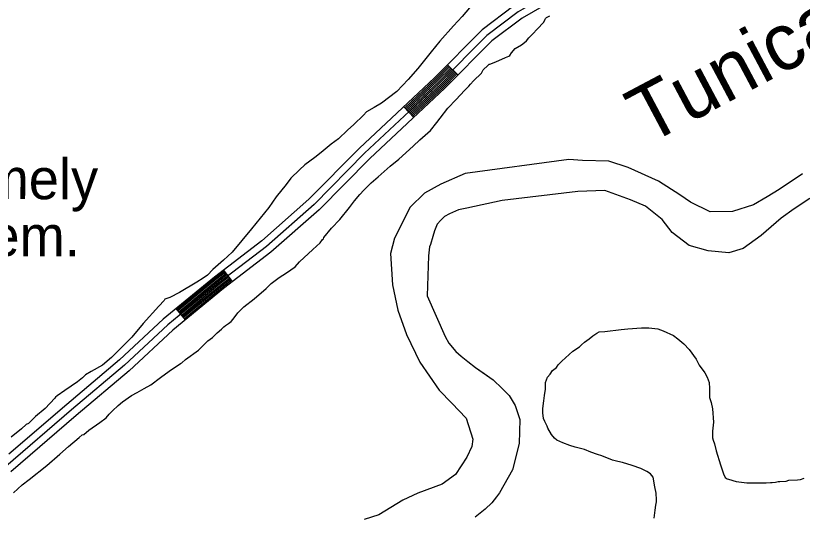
# Model space of a CAD drawing. Extents: x 3192986 to 3230865, y 867483 to 892886.
# Drawn here: x 3213297 to 3214907, y 882747 to 883775 of the extents above; entities that cross this region are included whole.
import ezdxf

# ---------------------------------------------------------------- set-up
doc = ezdxf.new("R2010")
doc.units = 0
for name, color, linetype in [('V-RIVR-IDEN', 7, 'Continuous'), ('V-ROAD-CNTR', 7, 'Continuous'), ('V-SITE-OTLN-IDEN', 7, 'Continuous'), ('V-SITE-VEGE', 7, 'Continuous'), ('V-TOPO-SHOR', 7, 'Continuous')]:
    doc.layers.add(name, color=color, linetype=linetype)

msp = doc.modelspace()

# ---------------------------------------------------------------- linework, layer by layer
at = {"layer": 'V-ROAD-CNTR'}
for p, q in [((3214202.3, 883653.8), (3214181, 883674.9)), ((3214111.7, 883566.9), (3214091.2, 883588.8)), ((3213740.6, 883230.5), (3213722.4, 883254.3)), ((3213644.1, 883151.9), (3213625, 883175.1))]:
    msp.add_line(p, q, dxfattribs=at)
for points in [[(3214950.3, 884340.7), (3214884, 884293.4), (3214837.6, 884267.8), (3214768.4, 884239.4), (3214700.1, 884199.6), (3214637.4, 884164.4), (3214595.7, 884124.3), (3214555.7, 884067.5), (3214532, 884005.1), (3214517.8, 883962.4), (3214490.3, 883932.5), (3214450.2, 883888.4), (3214388.7, 883837.2), (3214317, 883795.5), (3214251.6, 883746.2), (3214154.3, 883648), (3214000.7, 883504), (3213897.2, 883399.3), (3213800.4, 883313.9), (3213703.5, 883239.8), (3213598.5, 883153.2), (3213509.2, 883070.4), (3213401.1, 882978.8), (3213282.5, 882876.9)], [(3214959.1, 884328.6), (3214892, 884280.7), (3214844.1, 884254.2), (3214775.1, 884225.9), (3214707.6, 884186.6), (3214646.4, 884152.2), (3214607.1, 884114.4), (3214569, 884060.4), (3214546.2, 884000), (3214531, 883954.6), (3214501.3, 883922.3), (3214460.6, 883877.6), (3214397.3, 883824.8), (3214325.4, 883783), (3214261.5, 883734.9), (3214164.8, 883637.2), (3214011.1, 883493.3), (3213907.5, 883388.4), (3213809.9, 883302.3), (3213712.8, 883228), (3213608.4, 883141.9), (3213519.1, 883059.2), (3213410.8, 882967.4), (3213276.1, 882851.6)], [(3214968, 884316.5), (3214900, 884267.9), (3214850.6, 884240.7), (3214781.7, 884212.4), (3214715, 884173.6), (3214655.4, 884140.1), (3214618.5, 884104.6), (3214582.4, 884053.3), (3214560.3, 883995), (3214544.2, 883946.8), (3214512.4, 883912.2), (3214471, 883866.7), (3214406, 883812.5), (3214333.7, 883770.4), (3214271.4, 883723.5), (3214175.3, 883626.5), (3214021.6, 883482.5), (3213917.8, 883377.5), (3213819.4, 883290.7), (3213722.1, 883216.3), (3213618.3, 883130.7), (3213529.1, 883047.9), (3213420.6, 882955.9), (3213286.3, 882840.6)], [(3214183.1, 883672.8), (3214156.4, 883645.8), (3214093.2, 883586.6)], [(3214185.3, 883670.7), (3214158.5, 883643.7), (3214095.3, 883584.4)], [(3214187.4, 883668.6), (3214160.6, 883641.5), (3214097.3, 883582.3)], [(3214189.5, 883666.5), (3214162.7, 883639.4), (3214099.4, 883580.1)], [(3214191.7, 883664.4), (3214164.8, 883637.2), (3214101.4, 883577.9)], [(3214193.8, 883662.2), (3214166.9, 883635.1), (3214103.5, 883575.7)], [(3214195.9, 883660.1), (3214169, 883632.9), (3214105.5, 883573.5)], [(3214198.1, 883658), (3214171.1, 883630.8), (3214107.6, 883571.3)], [(3214200.2, 883655.9), (3214173.2, 883628.6), (3214109.6, 883569.1)], [(3213724.2, 883251.9), (3213705.3, 883237.4), (3213626.9, 883172.8)], [(3213726.1, 883249.5), (3213707.2, 883235.1), (3213628.8, 883170.4)], [(3213727.9, 883247.1), (3213709.1, 883232.7), (3213630.7, 883168.1)], [(3213729.7, 883244.7), (3213710.9, 883230.4), (3213632.6, 883165.8)], [(3213731.5, 883242.4), (3213712.8, 883228), (3213634.6, 883163.5)], [(3213733.3, 883240), (3213714.7, 883225.7), (3213636.5, 883161.2)], [(3213735.2, 883237.6), (3213716.5, 883223.3), (3213638.4, 883158.9)], [(3213737, 883235.2), (3213718.4, 883221), (3213640.3, 883156.6)], [(3213738.8, 883232.8), (3213720.3, 883218.6), (3213642.2, 883154.2)]]:
    msp.add_lwpolyline(points, dxfattribs=at)
at = {"layer": 'V-SITE-VEGE'}
for p, q in [((3214383.8, 883771.6), (3214390.4, 883775.3)), ((3214364.6, 883747.4), (3214378, 883762.3)), ((3214378, 883762.3), (3214380.9, 883767.9)), ((3214380.9, 883767.9), (3214381.8, 883769.7)), ((3214381.8, 883769.7), (3214383.8, 883771.6)), ((3214355.9, 883738.1), (3214364.6, 883747.4)), ((3214338.7, 883720.4), (3214342.6, 883724.1)), ((3214342.6, 883724.1), (3214347.3, 883729.7)), ((3214347.3, 883729.7), (3214355.9, 883738.1)), ((3214312, 883699.1), (3214319.7, 883708.4)), ((3214319.7, 883708.4), (3214332.1, 883715.8)), ((3214332.1, 883715.8), (3214338.7, 883720.4)), ((3214299.7, 883689.9), (3214306.3, 883692.6)), ((3214306.3, 883692.6), (3214308.2, 883693.5)), ((3214308.2, 883693.5), (3214312, 883699.1)), ((3214263.6, 883673.4), (3214266.5, 883676.2)), ((3214266.5, 883676.2), (3214267.4, 883676.2)), ((3214267.4, 883676.2), (3214279.7, 883680.7)), ((3214279.7, 883680.7), (3214299.7, 883689.9)), ((3214250.2, 883657.6), (3214254.1, 883664.2)), ((3214254.1, 883664.2), (3214263.6, 883673.4)), ((3214234, 883641.8), (3214250.2, 883657.6)), ((3214215.8, 883622.3), (3214224.4, 883630.7)), ((3214224.4, 883630.7), (3214228.2, 883635.3)), ((3214228.2, 883635.3), (3214234, 883641.8)), ((3214198.5, 883603.7), (3214215.8, 883622.3)), ((3214181.3, 883586), (3214198.5, 883603.7)), ((3214166, 883565.5), (3214181.3, 883586)), ((3214159.2, 883556.2), (3214166, 883565.5)), ((3214145.8, 883540.4), (3214159.2, 883556.2)), ((3214123.9, 883520.9), (3214145.8, 883540.4)), ((3214110.5, 883507.9), (3214123.9, 883520.9)), ((3214080.9, 883481), (3214110.5, 883507.9)), ((3214038.9, 883444.9), (3214063.7, 883467.1)), ((3214063.7, 883467.1), (3214080.9, 883481)), ((3214429.1, 883480.5), (3214217.3, 883451.9)), ((3214457.1, 883478.3), (3214429.1, 883480.5)), ((3214511.3, 883477.5), (3214457.1, 883478.3)), ((3214550.9, 883464.3), (3214511.3, 883477.5)), ((3214217.3, 883451.9), (3214167.3, 883430)), ((3214612.9, 883436.3), (3214550.9, 883464.3)), ((3214907.7, 883451), (3214860.2, 883419.2)), ((3214024.6, 883432.8), (3214038.9, 883444.9)), ((3214656.7, 883408.5), (3214612.9, 883436.3)), ((3214001.6, 883408.7), (3214009.3, 883418)), ((3214009.3, 883418), (3214024.6, 883432.8)), ((3214167.3, 883430), (3214133.6, 883411.5)), ((3214860.2, 883419.2), (3214835.6, 883404.1)), ((3213990.2, 883395.6), (3214001.6, 883408.7)), ((3214133.6, 883411.5), (3214104.3, 883383)), ((3214447.7, 883415), (3214292.9, 883396.4)), ((3214502.9, 883416.9), (3214447.7, 883415)), ((3214555.9, 883398), (3214502.9, 883416.9)), ((3214678.2, 883392.9), (3214656.7, 883408.5)), ((3214835.6, 883404.1), (3214807.3, 883387.4)), ((3213980.5, 883382.6), (3213990.2, 883395.6)), ((3214292.9, 883396.4), (3214220.4, 883381.2)), ((3214586.5, 883385), (3214555.9, 883398)), ((3214718.6, 883373.3), (3214678.2, 883392.9)), ((3214807.3, 883387.4), (3214764.7, 883374.4)), ((3214922.8, 883400.9), (3214890.9, 883379.7)), ((3213960.4, 883357.4), (3213980.5, 883382.6)), ((3214104.3, 883383), (3214072.6, 883319.3)), ((3214203.7, 883377.4), (3214185.1, 883369.4)), ((3214220.4, 883381.2), (3214203.7, 883377.4)), ((3214620.4, 883357.4), (3214586.5, 883385)), ((3214764.7, 883374.4), (3214718.6, 883373.3)), ((3214890.9, 883379.7), (3214864.4, 883360.2)), ((3213943.2, 883339.8), (3213960.4, 883357.4)), ((3214166.9, 883356.1), (3214160, 883347.8)), ((3214175, 883363.9), (3214166.9, 883356.1)), ((3214185.1, 883369.4), (3214175, 883363.9)), ((3214640.8, 883330.9), (3214620.4, 883357.4)), ((3214864.4, 883360.2), (3214823.2, 883324.6)), ((3213927.8, 883321.1), (3213943.2, 883339.8)), ((3214160, 883347.8), (3214154.6, 883334.6)), ((3214150.8, 883323.1), (3214146.2, 883306.4)), ((3214154.6, 883334.6), (3214150.8, 883323.1)), ((3214675.7, 883304.2), (3214640.8, 883330.9)), ((3214823.2, 883324.6), (3214786.7, 883298)), ((3213904.9, 883296), (3213920.1, 883309.9)), ((3213920.1, 883309.9), (3213924.9, 883316.5)), ((3213924.9, 883316.5), (3213926.9, 883318.3)), ((3213926.9, 883318.3), (3213927.8, 883321.1)), ((3214072.6, 883319.3), (3214064, 883287.8)), ((3214146.2, 883306.4), (3214144.3, 883301.8)), ((3213878.1, 883271), (3213904.9, 883296)), ((3214144.3, 883301.8), (3214142.2, 883282.9)), ((3214714.4, 883293.7), (3214675.7, 883304.2)), ((3214756.8, 883289.4), (3214714.4, 883293.7)), ((3214786.7, 883298), (3214756.8, 883289.4)), ((3214064, 883287.8), (3214068.5, 883223.6)), ((3214142.2, 883282.9), (3214139.2, 883201.6)), ((3213851.4, 883248.7), (3213868.6, 883260.7)), ((3213868.6, 883260.7), (3213878.1, 883271)), ((3213836.2, 883238.6), (3213851.4, 883248.7)), ((3213809.5, 883216.4), (3213820, 883226.6)), ((3213820, 883226.6), (3213833.3, 883236.8)), ((3213833.3, 883236.8), (3213836.2, 883238.6)), ((3213784.7, 883195.1), (3213809.5, 883216.4)), ((3214068.5, 883223.6), (3214079.5, 883171.9)), ((3213763.7, 883178.4), (3213784.7, 883195.1)), ((3214139.2, 883201.6), (3214176, 883117.9)), ((3213751.3, 883166.3), (3213763.7, 883178.4)), ((3213741.7, 883153.3), (3213751.3, 883166.3)), ((3214079.5, 883171.9), (3214096.9, 883122)), ((3213726.4, 883140.3), (3213732.1, 883144.9)), ((3213732.1, 883144.9), (3213737.9, 883148.6)), ((3213737.9, 883148.6), (3213741.7, 883153.3)), ((3213709.3, 883125.5), (3213717.8, 883132.9)), ((3213717.8, 883132.9), (3213722.6, 883137.5)), ((3213722.6, 883137.5), (3213726.4, 883140.3)), ((3214491.4, 883127.7), (3214503.4, 883128.4)), ((3214503.4, 883128.4), (3214536.5, 883132.5)), ((3214536.5, 883132.5), (3214550.3, 883133.3)), ((3214550.3, 883133.3), (3214577.9, 883135.6)), ((3214577.9, 883135.6), (3214593.5, 883135.4)), ((3214593.5, 883135.4), (3214611.8, 883133.3)), ((3214611.8, 883133.3), (3214622.8, 883129.5)), ((3214622.8, 883129.5), (3214643.8, 883120)), ((3213690.2, 883108.8), (3213699.7, 883116.2)), ((3213699.7, 883116.2), (3213709.3, 883125.5)), ((3214096.9, 883122), (3214124.1, 883065.6)), ((3214176, 883117.9), (3214183.9, 883104.3)), ((3214461.7, 883106.1), (3214471, 883113.3)), ((3214471, 883113.3), (3214478.4, 883119.6)), ((3214478.4, 883119.6), (3214486.8, 883125)), ((3214486.8, 883125), (3214491.4, 883127.7)), ((3214643.8, 883120), (3214652.9, 883113.4)), ((3214652.9, 883113.4), (3214664.7, 883103.1)), ((3213671.1, 883090.2), (3213690.2, 883108.8)), ((3214183.9, 883104.3), (3214198.1, 883086.9)), ((3214437.6, 883088), (3214451.5, 883097)), ((3214451.5, 883097), (3214455.2, 883100.6)), ((3214455.2, 883100.6), (3214461.7, 883106.1)), ((3214664.7, 883103.1), (3214675.5, 883091)), ((3213644.4, 883070.8), (3213671.1, 883090.2)), ((3214198.1, 883086.9), (3214208.8, 883077.7)), ((3214415.2, 883067.2), (3214437.6, 883088)), ((3214675.5, 883091), (3214689.9, 883071.5)), ((3213633.9, 883062.5), (3213636.8, 883064.3)), ((3213636.8, 883064.3), (3213644.4, 883070.8)), ((3214124.1, 883065.6), (3214163.9, 883008.1)), ((3214208.8, 883077.7), (3214222.2, 883066.7)), ((3214222.2, 883066.7), (3214238.3, 883054.7)), ((3214407.8, 883060), (3214415.2, 883067.2)), ((3214689.9, 883071.5), (3214696.2, 883059.5)), ((3213611.1, 883046.8), (3213633.9, 883062.5)), ((3214238.3, 883054.7), (3214274.1, 883028.9)), ((3214391, 883040.9), (3214395.7, 883048.2)), ((3214395.7, 883048.2), (3214404, 883054.5)), ((3214404, 883054.5), (3214407.8, 883060)), ((3214696.2, 883059.5), (3214707.9, 883043.7)), ((3213573, 883019.1), (3213593, 883033.9)), ((3213593, 883033.9), (3213611.1, 883046.8)), ((3214381.5, 883023.6), (3214385.4, 883034.6)), ((3214385.4, 883034.6), (3214391, 883040.9)), ((3214707.9, 883043.7), (3214712.4, 883034.5)), ((3214712.4, 883034.5), (3214716.8, 883023.4)), ((3213559.7, 883011.7), (3213573, 883019.1)), ((3214274.1, 883028.9), (3214292.8, 883011.4)), ((3214381.3, 883009.8), (3214381.5, 883023.6)), ((3214716.8, 883023.4), (3214717.5, 883011.4)), ((3213534, 882997), (3213545.4, 883003.4)), ((3213545.4, 883003.4), (3213559.7, 883011.7)), ((3214163.9, 883008.1), (3214189.8, 882981.5)), ((3214292.8, 883011.4), (3214307.1, 882996.8)), ((3214379.3, 882997), (3214381.3, 883009.8)), ((3214717.5, 883011.4), (3214717.3, 882993.1)), ((3213506.4, 882976.7), (3213515, 882984.1)), ((3213515, 882984.1), (3213534, 882997)), ((3214307.1, 882996.8), (3214319.4, 882976.7)), ((3214376.2, 882970.4), (3214378.2, 882986)), ((3214378.2, 882986), (3214379.3, 882997)), ((3214717.3, 882993.1), (3214720.8, 882982.9)), ((3213495, 882965.5), (3213506.4, 882976.7)), ((3214189.8, 882981.5), (3214219.1, 882950.3)), ((3214319.4, 882976.7), (3214329, 882947.7)), ((3214376, 882961.2), (3214376.2, 882970.4)), ((3214720.8, 882982.9), (3214723.4, 882970)), ((3214723.4, 882970), (3214725.7, 882942.4)), ((3213469.2, 882941.4), (3213481.6, 882951.6)), ((3213481.6, 882951.6), (3213488.3, 882959)), ((3213488.3, 882959), (3213495, 882965.5)), ((3214377.7, 882950.2), (3214376, 882961.2)), ((3213446.3, 882925.7), (3213469.2, 882941.4)), ((3214219.1, 882950.3), (3214233, 882907.7)), ((3214329, 882947.7), (3214327.4, 882898.9)), ((3214380.4, 882943.7), (3214377.7, 882950.2)), ((3214384.8, 882934.5), (3214380.4, 882943.7)), ((3214725.7, 882942.4), (3214723.6, 882924.1)), ((3213435.8, 882917.4), (3213446.3, 882925.7)), ((3214386.6, 882929.9), (3214384.8, 882934.5)), ((3214393.8, 882916.9), (3214386.6, 882929.9)), ((3214723.6, 882924.1), (3214723.4, 882910.3)), ((3213404.4, 882892.4), (3213426.3, 882910.9)), ((3213426.3, 882910.9), (3213433, 882916.5)), ((3213433, 882916.5), (3213435.8, 882917.4)), ((3214233, 882907.7), (3214230.9, 882892.3)), ((3214400.1, 882909.5), (3214393.8, 882916.9)), ((3214404.6, 882905.7), (3214400.1, 882909.5)), ((3214417.4, 882900), (3214404.6, 882905.7)), ((3214723.4, 882910.3), (3214725.2, 882905.7)), ((3214725.2, 882905.7), (3214727.9, 882898.3)), ((3213387.2, 882876.6), (3213404.4, 882892.4)), ((3214230.9, 882892.3), (3214220.7, 882870.8)), ((3214327.4, 882898.9), (3214313.9, 882844.9)), ((3214431.1, 882894.3), (3214417.4, 882900)), ((3214442.1, 882891.4), (3214431.1, 882894.3)), ((3214461.3, 882886.5), (3214442.1, 882891.4)), ((3214474.1, 882880.8), (3214461.3, 882886.5)), ((3214727.9, 882898.3), (3214731.3, 882883.6)), ((3213360.5, 882853.5), (3213387.2, 882876.6)), ((3214220.7, 882870.8), (3214197.6, 882835)), ((3214487.8, 882876), (3214474.1, 882880.8)), ((3214496.9, 882873.2), (3214487.8, 882876)), ((3214518.9, 882864.6), (3214496.9, 882873.2)), ((3214731.3, 882883.6), (3214740.1, 882855)), ((3214529.8, 882861.7), (3214518.9, 882864.6)), ((3214539, 882859.7), (3214529.8, 882861.7)), ((3214559.1, 882853.9), (3214539, 882859.7)), ((3214740.1, 882855), (3214746.3, 882836.5)), ((3213324.3, 882824.8), (3213360.5, 882853.5)), ((3214313.9, 882844.9), (3214287.1, 882797.4)), ((3214576.5, 882847.2), (3214559.1, 882853.9)), ((3214589.3, 882841.5), (3214576.5, 882847.2)), ((3214596.5, 882836.8), (3214589.3, 882841.5)), ((3213310, 882813.7), (3213324.3, 882824.8)), ((3214197.6, 882835), (3214170.2, 882815.5)), ((3214602, 882829.4), (3214596.5, 882836.8)), ((3214605.3, 882810.1), (3214602, 882829.4)), ((3214746.3, 882836.5), (3214749.8, 882829.1)), ((3214749.8, 882829.1), (3214753.5, 882826.3)), ((3214753.5, 882826.3), (3214756.2, 882825.3)), ((3214756.2, 882825.3), (3214771.8, 882820.5)), ((3214874.6, 882821.8), (3214880.2, 882823.6)), ((3214880.2, 882823.6), (3214897.6, 882824.2)), ((3214897.6, 882824.2), (3214904.1, 882825.1)), ((3214904.1, 882825.1), (3214911.5, 882827.7)), ((3213291.8, 882797.9), (3213310, 882813.7)), ((3214170.2, 882815.5), (3214120.2, 882797.2)), ((3214607.9, 882797.2), (3214605.3, 882810.1)), ((3214771.8, 882820.5), (3214793.8, 882818.4)), ((3214793.8, 882818.4), (3214833.3, 882817.8)), ((3214833.3, 882817.8), (3214842.5, 882818.6)), ((3214842.5, 882818.6), (3214846.1, 882818.5)), ((3214846.1, 882818.5), (3214852.6, 882819.4)), ((3214852.6, 882819.4), (3214858.1, 882821.1)), ((3214858.1, 882821.1), (3214861.8, 882821.1)), ((3214861.8, 882821.1), (3214874.6, 882821.8)), ((3214120.2, 882797.2), (3214089.3, 882782.3)), ((3214287.1, 882797.4), (3214281.5, 882789.3)), ((3214608.6, 882783.4), (3214607.9, 882797.2)), ((3214089.3, 882782.3), (3214040.1, 882752.3)), ((3214271.4, 882776.8), (3214257.7, 882764.4)), ((3214281.5, 882789.3), (3214271.4, 882776.8)), ((3214607.6, 882772.4), (3214608.6, 882778.8)), ((3214608.6, 882778.8), (3214608.6, 882783.4)), ((3214257.7, 882764.4), (3214237.5, 882747.5)), ((3214604.4, 882745.8), (3214606.5, 882762.3)), ((3214606.5, 882762.3), (3214607.6, 882772.4)), ((3214040.1, 882752.3), (3214010.1, 882742.8))]:
    msp.add_line(p, q, dxfattribs=at)
for points in [[(3214225.8, 883791.7), (3214210.8, 883773.6), (3214193.1, 883754.5), (3214165.1, 883722.8), (3214147.3, 883701), (3214120.2, 883667.4), (3214100.6, 883644.7), (3214077.2, 883620.3), (3214045.7, 883595.9), (3214030.8, 883586.9), (3214015.1, 883578), (3214008.6, 883571.6), (3213989, 883552.6), (3213976, 883540.9), (3213957.4, 883522.8), (3213942.5, 883512), (3213922, 883494.8), (3213909, 883484.9), (3213888.6, 883469.6), (3213877.5, 883459.6), (3213859.8, 883442.4), (3213850.4, 883429.7), (3213829.8, 883404.3), (3213814.8, 883382.4), (3213779.3, 883338.9), (3213740, 883290.7), (3213722.3, 883274.5), (3213700, 883255.5), (3213689.7, 883243.7), (3213680.5, 883237.4), (3213667.5, 883229.3), (3213632.3, 883207.8)], [(3213632.3, 883207.8), (3213611.9, 883198), (3213601.8, 883194.4), (3213600.8, 883191.7), (3213589.6, 883179.9), (3213557.9, 883144.6), (3213534.5, 883116.4), (3213514.9, 883096.5)], [(3213514.9, 883096.5), (3213513.1, 883095.6), (3213492.6, 883074.8), (3213474, 883059.4), (3213450.8, 883046), (3213439.7, 883039.7), (3213433.2, 883033.4), (3213423, 883025.2), (3213397, 883007.2), (3213381.2, 882996.5), (3213378.4, 882993.7), (3213376.6, 882991.9), (3213357, 882970.2), (3213337.4, 882953.9), (3213322.5, 882939.4), (3213317.9, 882937.7), (3213308.6, 882928.6), (3213287.2, 882911.5)]]:
    msp.add_lwpolyline(points, dxfattribs=at)
at = {"layer": 'V-TOPO-SHOR'}
for points in [[(3214907.7, 883451), (3214860.2, 883419.2), (3214835.6, 883404.1), (3214807.3, 883387.4), (3214764.7, 883374.4), (3214718.6, 883373.3), (3214678.2, 883392.9), (3214656.7, 883408.5), (3214612.9, 883436.3), (3214550.9, 883464.3), (3214511.3, 883477.5), (3214457.1, 883478.3), (3214429.1, 883480.5), (3214217.3, 883451.9), (3214167.3, 883430), (3214133.6, 883411.5), (3214104.3, 883383), (3214072.6, 883319.3), (3214064, 883287.8), (3214068.5, 883223.6), (3214079.5, 883171.9), (3214096.9, 883122), (3214124.1, 883065.6), (3214163.9, 883008.1), (3214189.8, 882981.5), (3214219.1, 882950.3), (3214233, 882907.7), (3214230.9, 882892.3), (3214220.7, 882870.8), (3214197.6, 882835), (3214170.2, 882815.5), (3214120.2, 882797.2), (3214089.3, 882782.3), (3214040.1, 882752.3), (3214010.1, 882742.8)], [(3214922.8, 883400.9), (3214890.9, 883379.7), (3214864.4, 883360.2), (3214823.2, 883324.6), (3214786.7, 883298), (3214756.8, 883289.4), (3214714.4, 883293.7), (3214675.7, 883304.2), (3214640.8, 883330.9), (3214620.4, 883357.4), (3214586.5, 883385), (3214555.9, 883398), (3214502.9, 883416.9), (3214447.7, 883415), (3214292.9, 883396.4), (3214220.4, 883381.2), (3214203.7, 883377.4)], [(3214203.7, 883377.4), (3214185.1, 883369.4), (3214175, 883363.9), (3214166.9, 883356.1), (3214160, 883347.8), (3214154.6, 883334.6), (3214150.8, 883323.1), (3214146.2, 883306.4)], [(3214146.2, 883306.4), (3214144.3, 883301.8), (3214142.2, 883282.9), (3214139.2, 883201.6), (3214176, 883117.9), (3214183.9, 883104.3), (3214198.1, 883086.9), (3214208.8, 883077.7), (3214222.2, 883066.7), (3214238.3, 883054.7), (3214256.2, 883041.8), (3214274.1, 883028.9), (3214292.8, 883011.4), (3214307.1, 882996.8), (3214319.4, 882976.7), (3214329, 882947.7), (3214327.4, 882898.9), (3214313.9, 882844.9), (3214287.1, 882797.4), (3214281.5, 882789.3), (3214271.4, 882776.8), (3214257.7, 882764.4), (3214237.5, 882747.5)]]:
    msp.add_lwpolyline(points, dxfattribs=at)

# ---------------------------------------------------------------- texts
at = {"layer": 'V-RIVR-IDEN'}
msp.add_text('Tunica', height=116, rotation=27.951, dxfattribs=at).set_placement((3214590.1, 883509.5))
at = {"layer": 'V-SITE-OTLN-IDEN'}
msp.add_text('Comely', height=83, rotation=359.7093, dxfattribs=at).set_placement((3213088.9, 883400.6))
msp.add_text('Cem.', height=83, dxfattribs=at).set_placement((3213162.7, 883282.4))

doc.saveas('drawing.dxf')
